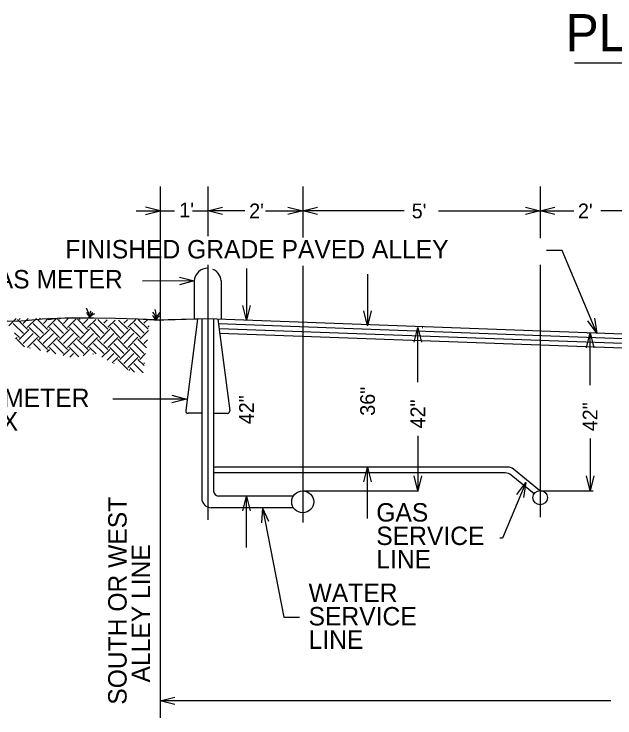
# Model space of a CAD drawing. Extents: x 524397 to 525117, y 3701341 to 3701821.
# Drawn here: x 524465.7 to 524531, y 3701447.8 to 3701524.2 of the extents above; entities that cross this region are included whole.
import ezdxf

# ---------------------------------------------------------------- set-up
doc = ezdxf.new("R2010")
doc.units = 0
doc.layers.add('Level 1', color=7, linetype='Continuous')
doc.layers.add('Level 11', color=7, linetype='Continuous')

msp = doc.modelspace()

# ---------------------------------------------------------------- linework, layer by layer
at = {"layer": 'Level 1'}
for p, q in [((524526.598, 3701518.966), (524539.734, 3701518.966)), ((524481.605, 3701505.51), (524481.605, 3701447.82)), ((524486.759, 3701505.51), (524486.759, 3701500.146)), ((524497.074, 3701505.51), (524497.074, 3701499.992)), ((524522.855, 3701505.51), (524522.855, 3701499.933)), ((524486.759, 3701497.028), (524486.759, 3701469.343)), ((524497.074, 3701496.911), (524497.074, 3701469.049)), ((524522.855, 3701497.029), (524522.855, 3701469.603)), ((524485.286, 3701495.267), (524485.286, 3701491.122)), ((524488.225, 3701495.299), (524488.225, 3701491.108)), ((524466.022, 3701490.858), (524462.605, 3701490.989)), ((524465.163, 3701490.387), (524465.968, 3701491.191)), ((524465.653, 3701490.658), (524466.747, 3701489.565)), ((524466.942, 3701490.923), (524466.022, 3701490.858)), ((524466.091, 3701491.096), (524467.185, 3701490.002)), ((524466.294, 3701491.095), (524466.393, 3701491.195)), ((524466.731, 3701490.658), (524467.276, 3701491.202)), ((524468.781, 3701491.12), (524466.942, 3701490.923)), ((524467.169, 3701490.22), (524468.158, 3701491.21)), ((524467.825, 3701490.658), (524468.919, 3701489.564)), ((524468.263, 3701491.095), (524469.357, 3701490.002)), ((524468.482, 3701491.095), (524468.599, 3701491.213)), ((524472.067, 3701491.251), (524468.781, 3701491.12)), ((524468.919, 3701490.658), (524469.477, 3701491.215)), ((524469.357, 3701490.22), (524470.339, 3701491.203)), ((524470.424, 3701491.186), (524469.431, 3701491.039)), ((524470.021, 3701490.666), (524471.115, 3701489.572)), ((524474.4, 3701491.219), (524470.424, 3701491.186)), ((524470.458, 3701491.104), (524471.552, 3701490.01)), ((524470.661, 3701491.103), (524470.756, 3701491.197)), ((524471.099, 3701490.666), (524471.618, 3701491.185)), ((524471.537, 3701490.228), (524472.47, 3701491.162)), ((524476.732, 3701491.186), (524472.067, 3701491.251)), ((524472.193, 3701490.666), (524473.287, 3701489.572)), ((524472.63, 3701491.103), (524473.724, 3701490.009)), ((524472.849, 3701491.103), (524472.896, 3701491.15)), ((524473.287, 3701490.666), (524473.748, 3701491.127)), ((524473.724, 3701490.228), (524474.596, 3701491.1)), ((524474.389, 3701490.674), (524475.482, 3701489.58)), ((524476.732, 3701491.186), (524474.4, 3701491.219)), ((524474.846, 3701491.091), (524475.92, 3701490.017)), ((524475.467, 3701490.673), (524475.849, 3701491.056)), ((524475.904, 3701490.236), (524476.695, 3701491.027)), ((524476.56, 3701490.673), (524477.654, 3701489.579)), ((524479.164, 3701491.12), (524476.732, 3701491.186)), ((524479.164, 3701491.12), (524476.732, 3701491.186)), ((524477.08, 3701491.029), (524478.092, 3701490.017)), ((524477.654, 3701490.673), (524478.038, 3701491.057)), ((524478.092, 3701490.236), (524478.94, 3701491.084)), ((524478.756, 3701490.681), (524479.85, 3701489.588)), ((524481.989, 3701491.022), (524479.164, 3701491.12)), ((524481.529, 3701490.989), (524479.164, 3701491.12)), ((524479.22, 3701491.092), (524480.287, 3701490.025)), ((524479.834, 3701490.681), (524480.277, 3701491.123)), ((524482.449, 3701491.055), (524481.529, 3701490.989)), ((524485.66, 3701491.13), (524481.989, 3701491.022)), ((524486.759, 3701491.156), (524482.449, 3701491.055)), ((524485.66, 3701491.13), (524484.371, 3701481.196)), ((524486.115, 3701491.156), (524486.115, 3701471.678)), ((524533.168, 3701489.455), (524486.759, 3701491.156)), ((524487.403, 3701491.156), (524487.403, 3701472.433)), ((524487.859, 3701491.12), (524489.15, 3701481.172)), ((524466.294, 3701488.908), (524467.388, 3701490.002)), ((524467.388, 3701490.22), (524468.482, 3701489.127)), ((524468.474, 3701488.916), (524469.568, 3701490.009)), ((524469.583, 3701490.229), (524470.677, 3701489.135)), ((524470.661, 3701488.916), (524471.755, 3701490.009)), ((524471.755, 3701490.228), (524472.849, 3701489.134)), ((524472.841, 3701488.923), (524473.935, 3701490.017)), ((524473.951, 3701490.236), (524475.045, 3701489.142)), ((524475.029, 3701488.923), (524476.123, 3701490.017)), ((524476.123, 3701490.236), (524477.217, 3701489.142)), ((524477.209, 3701488.931), (524478.303, 3701490.025)), ((524478.319, 3701490.244), (524479.412, 3701489.15)), ((524479.397, 3701488.931), (524480.344, 3701489.878)), ((524480.272, 3701490.243), (524480.409, 3701490.381)), ((524533.151, 3701488.939), (524487.926, 3701490.601)), ((524533.134, 3701488.423), (524487.994, 3701490.083)), ((524510.025, 3701490.229), (524510.122, 3701490.229)), ((524465.784, 3701489.652), (524466.31, 3701489.127)), ((524465.91, 3701488.962), (524466.075, 3701489.127)), ((524466.731, 3701488.47), (524467.825, 3701489.564)), ((524467.177, 3701488.041), (524468.263, 3701489.127)), ((524468.911, 3701488.478), (524470.005, 3701489.572)), ((524469.349, 3701488.04), (524470.443, 3701489.134)), ((524471.099, 3701488.478), (524472.193, 3701489.572)), ((524471.537, 3701488.04), (524472.63, 3701489.134)), ((524473.279, 3701488.486), (524474.373, 3701489.579)), ((524473.716, 3701488.048), (524474.81, 3701489.142)), ((524475.467, 3701488.486), (524476.56, 3701489.579)), ((524475.904, 3701488.048), (524476.998, 3701489.142)), ((524477.647, 3701488.493), (524478.74, 3701489.587)), ((524478.084, 3701488.056), (524479.178, 3701489.15)), ((524533.117, 3701487.908), (524488.061, 3701489.565)), ((524528.073, 3701489.612), (524527.971, 3701489.612)), ((524466.075, 3701488.908), (524466.874, 3701488.109)), ((524467.833, 3701488.478), (524468.588, 3701487.724)), ((524468.271, 3701488.916), (524469.365, 3701487.822)), ((524470.005, 3701488.478), (524471.099, 3701487.384)), ((524470.443, 3701488.916), (524471.537, 3701487.822)), ((524472.201, 3701488.486), (524473.295, 3701487.392)), ((524472.638, 3701488.924), (524473.732, 3701487.83)), ((524474.373, 3701488.486), (524475.467, 3701487.392)), ((524474.81, 3701488.923), (524475.904, 3701487.829)), ((524476.568, 3701488.494), (524477.662, 3701487.4)), ((524477.006, 3701488.931), (524478.1, 3701487.837)), ((524478.74, 3701488.493), (524479.834, 3701487.399)), ((524479.178, 3701488.931), (524480.101, 3701488.008)), ((524479.834, 3701488.493), (524480.213, 3701488.873)), ((524467.396, 3701488.041), (524467.459, 3701487.978)), ((524469.308, 3701487.562), (524469.568, 3701487.822)), ((524469.568, 3701488.04), (524470.259, 3701487.349)), ((524471.082, 3701487.164), (524471.748, 3701487.829)), ((524471.763, 3701488.049), (524472.765, 3701487.046)), ((524473.241, 3701487.135), (524473.935, 3701487.829)), ((524473.935, 3701488.048), (524474.631, 3701487.353)), ((524475.275, 3701486.997), (524476.115, 3701487.837)), ((524476.131, 3701488.056), (524477.225, 3701486.962)), ((524477.209, 3701486.743), (524478.303, 3701487.837)), ((524478.303, 3701488.056), (524479.397, 3701486.962)), ((524471.797, 3701487.003), (524472.185, 3701487.392)), ((524474.318, 3701487.337), (524474.373, 3701487.392)), ((524475.839, 3701486.686), (524476.553, 3701487.399)), ((524476.403, 3701486.375), (524476.99, 3701486.962)), ((524477.647, 3701486.306), (524478.74, 3701487.399)), ((524478.084, 3701485.868), (524479.178, 3701486.962)), ((524479.389, 3701486.751), (524480.02, 3701487.382)), ((524476.553, 3701486.306), (524476.581, 3701486.277)), ((524476.99, 3701486.743), (524478.084, 3701485.649)), ((524478.748, 3701486.314), (524479.751, 3701485.311)), ((524479.186, 3701486.751), (524479.852, 3701486.085)), ((524479.826, 3701486.313), (524479.889, 3701486.376)), ((524478.2, 3701485.562), (524478.295, 3701485.657)), ((524478.311, 3701485.876), (524478.812, 3701485.375)), ((524486.115, 3701480.897), (524484.625, 3701480.905)), ((524488.893, 3701480.881), (524487.471, 3701480.889)), ((524519.296, 3701475.067), (524487.597, 3701475.067)), ((524522.784, 3701472.517), (524519.948, 3701474.835)), ((524519.055, 3701474.431), (524487.468, 3701474.431)), ((524522.198, 3701472.163), (524519.709, 3701474.198)), ((524497.074, 3701472.49), (524509.647, 3701472.49)), ((524522.855, 3701472.49), (524528.596, 3701472.49)), ((524492.912, 3701471.918), (524487.919, 3701471.918)), ((524496.061, 3701471.918), (524492.912, 3701471.918)), ((524492.449, 3701470.647), (524487.146, 3701470.647)), ((524496.061, 3701470.647), (524492.449, 3701470.647))]:
    msp.add_line(p, q, dxfattribs=at)
for centre, radius in [((524497.074, 3701471.283), 1.195), ((524522.855, 3701471.738), 0.782)]:
    msp.add_circle(centre, radius, dxfattribs=at)
for centre, radius, start, end in [((524486.757, 3701495.171), 1.474, 88.57272, 176.28672), ((524486.757, 3701495.171), 1.474, 5.03963, 67.3152), ((524470.947, 3701490.85), 3.017, 7.39936, 28.92321), ((524479.314, 3701491.519), 1.867, 344.17757, 20.94324), ((524471.676, 3701490.423), 2.404, 19.84424, 35.98671), ((524474.672, 3701491.481), 0.773, 140.16146, 198.20731), ((524474.675, 3701491.168), 0.741, 121.38392, 174.50133), ((524474.695, 3701490.888), 0.835, 104.73446, 155.14275), ((524479.683, 3701490.439), 1.537, 21.83055, 44.66088), ((524479.913, 3701491.075), 1.198, 356.90025, 42.71419), ((524482.963, 3701490.522), 1.917, 136.75222, 165.24199), ((524482.122, 3701490.451), 1.157, 116.72206, 151.07687), ((524484.627, 3701481.163), 0.258, 172.61934, 269.69485), ((524488.894, 3701481.139), 0.258, 269.67511, 7.39148), ((524487.597, 3701475.583), 0.516, 247.97237, 270), ((524519.295, 3701474.036), 1.031, 50.74061, 90), ((524487.468, 3701475.462), 1.031, 266.41514, 270), ((524519.055, 3701473.399), 1.031, 50.70261, 90), ((524487.919, 3701472.433), 0.516, 180, 270), ((524487.146, 3701471.678), 1.031, 180, 270)]:
    msp.add_arc(centre, radius, start, end, dxfattribs=at)
at = {"layer": 'Level 11'}
for p, q in [((524478.999, 3701502.874), (524483.146, 3701502.874)), ((524481.605, 3701502.874), (524480.004, 3701503.274)), ((524480.004, 3701502.474), (524481.605, 3701502.874)), ((524485.111, 3701502.874), (524486.759, 3701502.874)), ((524486.759, 3701502.874), (524488.36, 3701503.274)), ((524490.777, 3701502.874), (524486.759, 3701502.874)), ((524488.36, 3701502.474), (524486.759, 3701502.874)), ((524493.026, 3701502.874), (524497.074, 3701502.874)), ((524495.473, 3701503.274), (524497.074, 3701502.874)), ((524497.074, 3701502.874), (524495.473, 3701502.474)), ((524497.074, 3701502.874), (524498.675, 3701503.274)), ((524508.105, 3701502.874), (524497.074, 3701502.874)), ((524498.675, 3701502.474), (524497.074, 3701502.874)), ((524511.824, 3701502.874), (524522.855, 3701502.874)), ((524517.252, 3701502.874), (524522.855, 3701502.874)), ((524521.254, 3701503.274), (524522.855, 3701502.874)), ((524521.254, 3701503.274), (524522.855, 3701502.874)), ((524522.855, 3701502.874), (524521.254, 3701502.474)), ((524522.855, 3701502.874), (524521.254, 3701502.474)), ((524522.855, 3701502.874), (524524.456, 3701503.274)), ((524522.855, 3701502.874), (524526.502, 3701502.874)), ((524524.456, 3701502.474), (524522.855, 3701502.874)), ((524533.168, 3701502.874), (524529.447, 3701502.874)), ((524525.23, 3701498.564), (524523.542, 3701498.564)), ((524529.003, 3701489.601), (524525.23, 3701498.564)), ((524490.968, 3701496.616), (524490.968, 3701491.012)), ((524504.114, 3701496.015), (524504.114, 3701490.412)), ((524485.286, 3701495.267), (524479.688, 3701495.256)), ((524483.685, 3701495.664), (524485.286, 3701495.267)), ((524485.286, 3701495.267), (524483.686, 3701494.863)), ((524490.968, 3701491.012), (524490.568, 3701492.613)), ((524491.369, 3701492.613), (524490.968, 3701491.012)), ((524504.114, 3701490.412), (524503.714, 3701492.013)), ((524504.515, 3701492.013), (524504.114, 3701490.412)), ((524529.003, 3701489.601), (524528.013, 3701490.922)), ((524528.751, 3701491.232), (524529.003, 3701489.601)), ((524509.172, 3701488.631), (524509.572, 3701490.232)), ((524509.572, 3701484.267), (524509.572, 3701490.232)), ((524509.572, 3701490.232), (524509.972, 3701488.631)), ((524527.869, 3701488.021), (524528.269, 3701489.622)), ((524528.269, 3701483.962), (524528.269, 3701489.622)), ((524528.269, 3701489.622), (524528.67, 3701488.021)), ((524484.47, 3701482.451), (524476.459, 3701482.451)), ((524482.869, 3701482.851), (524484.47, 3701482.451)), ((524484.47, 3701482.451), (524482.869, 3701482.051)), ((524509.572, 3701478.455), (524509.572, 3701472.49)), ((524528.269, 3701478.15), (524528.269, 3701472.49)), ((524503.714, 3701473.466), (524504.114, 3701475.067)), ((524504.114, 3701469.464), (524504.114, 3701475.067)), ((524504.114, 3701475.067), (524504.515, 3701473.466)), ((524509.572, 3701472.49), (524509.172, 3701474.091)), ((524509.972, 3701474.091), (524509.572, 3701472.49)), ((524528.269, 3701472.49), (524527.869, 3701474.091)), ((524528.67, 3701474.091), (524528.269, 3701472.49)), ((524521.299, 3701473.397), (524518.78, 3701467.345)), ((524520.314, 3701472.073), (524521.299, 3701473.397)), ((524521.299, 3701473.397), (524521.053, 3701471.765)), ((524490.568, 3701470.317), (524490.968, 3701471.918)), ((524490.968, 3701466.314), (524490.968, 3701471.918)), ((524490.968, 3701471.918), (524491.369, 3701470.317)), ((524492.699, 3701470.647), (524492.616, 3701468.999)), ((524493.401, 3701469.154), (524492.699, 3701470.647)), ((524492.699, 3701470.647), (524495.028, 3701458.778)), ((524518.78, 3701467.345), (524518.478, 3701467.345)), ((524495.028, 3701458.778), (524496.713, 3701458.778)), ((524481.605, 3701449.691), (524483.206, 3701450.091)), ((524530.514, 3701449.691), (524481.605, 3701449.691)), ((524483.206, 3701449.29), (524481.605, 3701449.691))]:
    msp.add_line(p, q, dxfattribs=at)

# ---------------------------------------------------------------- texts
at = {"layer": 'Level 1'}
for s, height, p in [('PLAN', 4.0362, (524525.613, 3701520.213)), ('FINISHED GRADE PAVED ALLEY', 2, (524471.297, 3701497.718))]:
    msp.add_text(s, height=height, dxfattribs=at).set_placement(p)
at = {"layer": 'Level 11'}
for s, height, p in [("1'", 1.601, (524483.67, 3701502.181)), ("2'", 1.601, (524491.258, 3701502.074)), ("5'", 1.601, (524508.906, 3701502.074)), ("2'", 1.601, (524526.952, 3701502.074)), ('GAS METER', 2, (524461.778, 3701494.459)), ('WATER METER', 2, (524454.16, 3701481.573)), ('BOX', 2, (524460.52, 3701479.027)), ('GAS', 2, (524505.06, 3701469.142)), ('SERVICE', 2, (524505.06, 3701466.596)), ('LINE', 2, (524505.06, 3701464.05)), ('WATER', 2, (524497.71, 3701460.41)), ('SERVICE', 2, (524497.71, 3701457.864)), ('LINE', 2, (524497.71, 3701455.319))]:
    msp.add_text(s, height=height, dxfattribs=at).set_placement(p)
for s, height, p in [('36"', 1.601, (524504.915, 3701480.634)), ('42"', 1.601, (524491.769, 3701479.712)), ('42"', 1.601, (524510.372, 3701479.256)), ('42"', 1.601, (524529.07, 3701478.951)), ('SOUTH OR WEST', 2, (524477.955, 3701449.254)), ('ALLEY LINE', 2, (524480.501, 3701451.668))]:
    msp.add_text(s, height=height, rotation=90, dxfattribs=at).set_placement(p)

doc.saveas('drawing.dxf')
